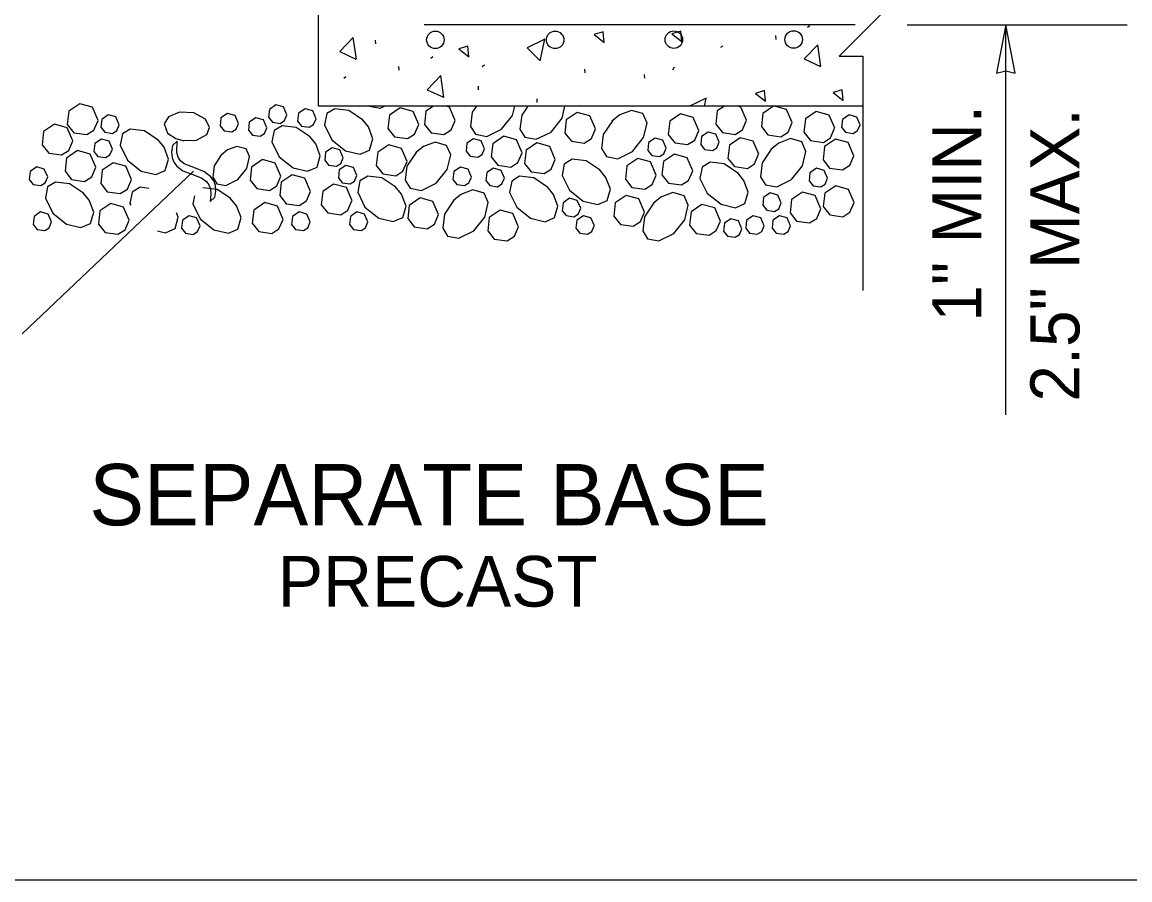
# Model space of a CAD drawing. Extents: x 99862 to 104211, y 98939 to 102076.
# Drawn here: x 100716.6 to 101077.6, y 99999.5 to 100279.2 of the extents above; entities that cross this region are included whole.
import ezdxf

# ---------------------------------------------------------------- set-up
doc = ezdxf.new("R2010")
doc.units = 0
for name, color, linetype in [('Level 1', 7, 'Continuous'), ('Level 15', 7, 'Continuous'), ('Level 17', 7, 'Continuous'), ('Level 18', 7, 'Continuous'), ('Level 19', 7, 'Continuous'), ('Level 20', 7, 'Continuous'), ('Level 23', 7, 'Continuous'), ('Level 7', 7, 'Continuous')]:
    doc.layers.add(name, color=color, linetype=linetype)

msp = doc.modelspace()

# ---------------------------------------------------------------- linework, layer by layer
at = {"layer": 'Level 1'}
msp.add_lwpolyline([(99862, 99999.5), (103151, 99999.5), (103151, 102075.5), (99862, 102075.5)], close=True, dxfattribs=at)
at = {"layer": 'Level 15'}
for p, q in [((101005.09, 100278.27), (101076.76, 100278.27)), ((101037.22, 100151.13), (101037.22, 100278.27)), ((100772.49, 100230.57), (100716.61, 100177.58))]:
    msp.add_line(p, q, dxfattribs=at)
msp.add_lwpolyline([(100990.61, 100319.79), (100990.61, 100283.53), (100998.35, 100283.53), (100982.86, 100268.05), (100990.61, 100268.05), (100990.61, 100191.69)], dxfattribs=at)
msp.add_lwpolyline([(101037.22, 100278.27), (101034.13, 100262.55), (101037.22, 100263.27), (101040.3, 100262.55)], close=True, dxfattribs=at)
at = {"layer": 'Level 17'}
for p, q in [((100813.22, 100251.79), (100813.22, 101461.47)), ((100990.61, 100251.79), (100813.22, 100251.79))]:
    msp.add_line(p, q, dxfattribs=at)
at = {"layer": 'Level 18'}
msp.add_line((100988.13, 100278.27), (100847.67, 100278.27), dxfattribs=at)
at = {"layer": 'Level 19'}
for p, q in [((100973.33, 100277.94), (100972.61, 100277.41)), ((100962.32, 100273.56), (100962.24, 100274.78)), ((100831.88, 100272.09), (100831.8, 100273.31)), ((100945, 100271.4), (100944.28, 100270.87)), ((100850.49, 100267.9), (100849.77, 100267.37)), ((100839.48, 100263.51), (100839.4, 100264.74)), ((100867.31, 100265.15), (100866.59, 100264.62)), ((100900.07, 100262.61), (100899.98, 100263.84)), ((100929.11, 100264.49), (100928.61, 100263.48)), ((100822.15, 100261.35), (100821.43, 100260.82)), ((100919.57, 100260.94), (100919.48, 100262.16)), ((100865.39, 100257.13), (100865.31, 100258.35)), ((100884.51, 100252.93), (100884.42, 100254.16))]:
    msp.add_line(p, q, dxfattribs=at)
for points in [[(100825.54, 100267.08), (100824.55, 100274.18), (100820.1, 100269.59), (100825.42, 100267.12)], [(100906.31, 100272.58), (100905.97, 100276.01), (100903, 100275.11), (100906.31, 100272.58)], [(100931.62, 100272.82), (100931.29, 100276.25), (100928.31, 100275.35), (100931.62, 100272.82)], [(100862.25, 100267.91), (100861.91, 100271.34), (100858.93, 100270.44), (100862.25, 100267.91)], [(100885.42, 100266.58), (100886.92, 100273.59), (100881.16, 100270.79), (100885.32, 100266.66)], [(100976.95, 100264.67), (100975.96, 100271.77), (100971.51, 100267.17), (100976.83, 100264.71)], [(100854.1, 100254.62), (100853.12, 100261.73), (100848.67, 100257.13), (100853.99, 100254.67)], [(100958.94, 100253.43), (100958.6, 100256.86), (100955.63, 100255.95), (100958.94, 100253.43)], [(100984.25, 100253.67), (100983.91, 100257.1), (100980.94, 100256.2), (100984.25, 100253.67)], [(100938.97, 100251.79), (100939.54, 100254.44), (100934.09, 100251.79)]]:
    msp.add_lwpolyline(points, dxfattribs=at)
at = {"layer": 'Level 20'}
for p, q in [((100765.57, 100238.94), (100765.32, 100236.8)), ((100767.11, 100240.39), (100765.57, 100238.94)), ((100767.04, 100236.7), (100767.11, 100240.39)), ((100765.32, 100236.8), (100765.46, 100235.03)), ((100765.46, 100235.03), (100766.01, 100233.51)), ((100767.47, 100235.11), (100767.04, 100236.7)), ((100768.25, 100233.92), (100767.47, 100235.11)), ((100766.01, 100233.51), (100767, 100232.17)), ((100767, 100232.17), (100768.95, 100230.66)), ((100769.45, 100233.01), (100768.25, 100233.92)), ((100771.7, 100232.13), (100769.45, 100233.01)), ((100775.81, 100230.52), (100771.7, 100232.13)), ((100768.95, 100230.66), (100772.78, 100229.25)), ((100772.78, 100229.25), (100775.16, 100228.31)), ((100775.16, 100228.31), (100776.71, 100227.19)), ((100778, 100228.9), (100775.81, 100230.52)), ((100776.71, 100227.19), (100777.49, 100226.1)), ((100779.04, 100227.48), (100778, 100228.9)), ((100779.62, 100225.88), (100779.04, 100227.48)), ((100777.49, 100226.1), (100777.95, 100224.82)), ((100777.95, 100224.82), (100778.08, 100223.09)), ((100779.44, 100222.13), (100779.75, 100224.09)), ((100779.75, 100224.09), (100779.62, 100225.88)), ((100778.08, 100223.09), (100777.9, 100220.67)), ((100777.9, 100220.67), (100779.44, 100222.13))]:
    msp.add_line(p, q, dxfattribs=at)
at = {"layer": 'Level 23'}
for points in [[(100741.35, 100247.11), (100739.52, 100251.41), (100735.37, 100252.55), (100731.8, 100250.14), (100731.33, 100245.81), (100733.46, 100243.1), (100737.67, 100242.52), (100740.02, 100243.99), (100741.35, 100247.11)], [(100748.27, 100245.68), (100747.17, 100248.26), (100744.68, 100248.94), (100742.54, 100247.49), (100742.25, 100244.9), (100743.54, 100243.27), (100746.06, 100242.92), (100747.47, 100243.81), (100748.27, 100245.68)], [(100769.09, 100240.56), (100773.47, 100240.73), (100776.76, 100242.54), (100777.7, 100244.81), (100776.41, 100247.57), (100772.55, 100249.63), (100767.89, 100249.84), (100764.26, 100248.31), (100762.88, 100245.97), (100763.96, 100243.02), (100766.73, 100241.19), (100769.28, 100240.53)], [(100787.14, 100246.18), (100786.04, 100248.75), (100783.55, 100249.44), (100781.41, 100247.99), (100781.12, 100245.39), (100782.4, 100243.77), (100784.93, 100243.42), (100786.34, 100244.3), (100787.14, 100246.17)], [(100802.93, 100248.94), (100801.83, 100251.52), (100799.34, 100252.2), (100797.21, 100250.75), (100796.92, 100248.15), (100798.2, 100246.53), (100800.73, 100246.18), (100802.14, 100247.07), (100802.93, 100248.94)], [(100812.42, 100247.66), (100811.31, 100250.24), (100808.82, 100250.92), (100806.69, 100249.48), (100806.4, 100246.88), (100807.68, 100245.25), (100810.21, 100244.9), (100811.62, 100245.79), (100812.41, 100247.66)], [(100827.57, 100247.37), (100823.07, 100250.37), (100818.47, 100250.94), (100815.88, 100249.35), (100815.17, 100245.67), (100817.55, 100240.81), (100822.05, 100237.22), (100826.78, 100236.12), (100829.86, 100237.46), (100830.92, 100241.18), (100829.47, 100245.03), (100827.4, 100247.54)], [(100829.77, 100251.79), (100833.31, 100251.11), (100834.71, 100251.79)], [(100845.86, 100245.78), (100844.02, 100250.08), (100839.87, 100251.21), (100836.31, 100248.81), (100835.83, 100244.48), (100837.96, 100241.77), (100842.18, 100241.19), (100844.53, 100242.66), (100845.85, 100245.78)], [(100846.85, 100251.79), (100846.91, 100251.78), (100846.92, 100251.79)], [(100850.63, 100251.79), (100848.21, 100250.16), (100847.73, 100245.83), (100849.87, 100243.12), (100854.08, 100242.54), (100856.43, 100244.02), (100857.76, 100247.13)], [(100857.76, 100247.13), (100855.93, 100251.43), (100854.62, 100251.79)], [(100864.66, 100251.79), (100863.33, 100249.79), (100862.76, 100245.19), (100864.35, 100242.61), (100868.03, 100241.9), (100872.89, 100244.27), (100876.48, 100248.78), (100877.18, 100251.79)], [(100881.38, 100251.79), (100879.44, 100248.87), (100878.87, 100244.26), (100880.45, 100241.68), (100884.13, 100240.97), (100888.99, 100243.35), (100892.58, 100247.85), (100893.5, 100251.79)], [(100903.51, 100244.34), (100901.68, 100248.64), (100897.53, 100249.77), (100893.97, 100247.36), (100893.49, 100243.03), (100895.62, 100240.32), (100899.83, 100239.74), (100902.19, 100241.22), (100903.51, 100244.34)], [(100909.03, 100247.05), (100906.03, 100242.55), (100905.46, 100237.94), (100907.05, 100235.36), (100910.73, 100234.65), (100915.59, 100237.03), (100919.18, 100241.53), (100920.28, 100246.26), (100918.94, 100249.34), (100915.21, 100250.39), (100911.37, 100248.94), (100908.86, 100246.88)], [(100937.2, 100243.83), (100935.37, 100248.13), (100931.22, 100249.26), (100927.66, 100246.85), (100927.18, 100242.52), (100929.31, 100239.81), (100933.52, 100239.23), (100935.88, 100240.71), (100937.2, 100243.83)], [(100945.52, 100251.79), (100943.18, 100250.21), (100942.7, 100245.87), (100944.83, 100243.16), (100949.04, 100242.58), (100951.39, 100244.06), (100952.72, 100247.18)], [(100952.72, 100247.18), (100950.89, 100251.48), (100949.75, 100251.79)], [(100961.52, 100251.79), (100958.04, 100249.44), (100957.57, 100245.11), (100959.7, 100242.4), (100963.91, 100241.82), (100966.26, 100243.29), (100967.59, 100246.41)], [(100967.59, 100246.41), (100965.76, 100250.71), (100961.81, 100251.79)], [(100981.44, 100244.59), (100979.6, 100248.89), (100975.45, 100250.02), (100971.89, 100247.61), (100971.41, 100243.28), (100973.55, 100240.57), (100977.76, 100239.99), (100980.11, 100241.47), (100981.43, 100244.59)], [(100989.72, 100245.67), (100988.62, 100248.25), (100986.13, 100248.93), (100983.99, 100247.49), (100983.7, 100244.89), (100984.99, 100243.26), (100987.51, 100242.92), (100988.92, 100243.8), (100989.72, 100245.67)], [(100733.16, 100240.46), (100731.32, 100244.76), (100727.18, 100245.89), (100723.61, 100243.48), (100723.13, 100239.15), (100725.27, 100236.44), (100729.48, 100235.86), (100731.83, 100237.34), (100733.16, 100240.46)], [(100796.37, 100244.73), (100795.27, 100247.32), (100792.78, 100248), (100790.64, 100246.55), (100790.35, 100243.95), (100791.64, 100242.33), (100794.16, 100241.98), (100795.57, 100242.87), (100796.37, 100244.74)], [(100810.44, 100241.83), (100805.93, 100244.82), (100801.33, 100245.39), (100798.75, 100243.81), (100798.04, 100240.12), (100800.41, 100235.26), (100804.92, 100231.67), (100809.65, 100230.58), (100812.72, 100231.91), (100813.78, 100235.64), (100812.33, 100239.48), (100810.27, 100241.99)], [(100760.96, 100240.74), (100756.46, 100243.74), (100751.85, 100244.31), (100749.27, 100242.72), (100748.56, 100239.04), (100750.94, 100234.18), (100755.44, 100230.59), (100760.17, 100229.49), (100763.25, 100230.83), (100764.3, 100234.55), (100762.85, 100238.4), (100760.79, 100240.91)], [(100879.54, 100236.52), (100877.71, 100240.82), (100873.56, 100241.95), (100869.99, 100239.54), (100869.51, 100235.21), (100871.65, 100232.5), (100875.86, 100231.92), (100878.21, 100233.4), (100879.54, 100236.52)], [(100943.8, 100240.04), (100942.7, 100242.62), (100940.21, 100243.3), (100938.07, 100241.86), (100937.78, 100239.26), (100939.06, 100237.63), (100941.59, 100237.29), (100943, 100238.17), (100943.8, 100240.04)], [(100746.03, 100237.76), (100744.93, 100240.33), (100742.44, 100241.01), (100740.3, 100239.57), (100740.01, 100236.97), (100741.29, 100235.35), (100743.82, 100235), (100745.23, 100235.88), (100746.03, 100237.75)], [(100781.62, 100235.97), (100779.19, 100232.32), (100778.73, 100228.6), (100780.01, 100226.5), (100782.99, 100225.93), (100786.93, 100227.85), (100789.84, 100231.5), (100790.72, 100235.33), (100789.65, 100237.82), (100786.62, 100238.68), (100783.51, 100237.51), (100781.48, 100235.84)], [(100821.23, 100234.94), (100820.13, 100237.52), (100817.64, 100238.2), (100815.5, 100236.76), (100815.22, 100234.16), (100816.5, 100232.53), (100819.02, 100232.18), (100820.44, 100233.07), (100821.23, 100234.94)], [(100842.07, 100233.72), (100840.23, 100238.02), (100836.08, 100239.15), (100832.52, 100236.75), (100832.04, 100232.41), (100834.18, 100229.71), (100838.39, 100229.12), (100840.74, 100230.6), (100842.07, 100233.72)], [(100845.04, 100236.71), (100842.04, 100232.2), (100841.47, 100227.6), (100843.06, 100225.01), (100846.74, 100224.3), (100851.6, 100226.68), (100855.19, 100231.18), (100856.29, 100235.91), (100854.95, 100238.99), (100851.23, 100240.05), (100847.38, 100238.6), (100844.87, 100236.53)], [(100867.33, 100237.91), (100866.23, 100240.48), (100863.73, 100241.17), (100861.6, 100239.72), (100861.31, 100237.12), (100862.59, 100235.5), (100865.12, 100235.15), (100866.53, 100236.03), (100867.33, 100237.9)], [(100890.39, 100234.38), (100888.56, 100238.68), (100884.41, 100239.81), (100880.85, 100237.4), (100880.37, 100233.07), (100882.51, 100230.36), (100886.71, 100229.78), (100889.07, 100231.26), (100890.39, 100234.37)], [(100926.54, 100238.08), (100925.43, 100240.66), (100922.95, 100241.34), (100920.81, 100239.9), (100920.52, 100237.3), (100921.8, 100235.67), (100924.33, 100235.33), (100925.74, 100236.21), (100926.53, 100238.08)], [(100956.67, 100236.08), (100954.83, 100240.38), (100950.68, 100241.51), (100947.12, 100239.1), (100946.64, 100234.77), (100948.78, 100232.06), (100952.99, 100231.48), (100955.34, 100232.96), (100956.66, 100236.08)], [(100960.85, 100237.84), (100957.85, 100233.34), (100957.28, 100228.74), (100958.87, 100226.15), (100962.55, 100225.44), (100967.41, 100227.82), (100971, 100232.32), (100972.09, 100237.05), (100970.76, 100240.13), (100967.04, 100241.19), (100963.19, 100239.74), (100960.68, 100237.67)], [(100987.66, 100235.62), (100985.83, 100239.93), (100981.68, 100241.06), (100978.11, 100238.65), (100977.64, 100234.32), (100979.77, 100231.61), (100983.98, 100231.03), (100986.33, 100232.51), (100987.66, 100235.63)], [(100740.63, 100231.84), (100738.79, 100236.14), (100734.64, 100237.28), (100731.08, 100234.87), (100730.6, 100230.54), (100732.74, 100227.83), (100736.95, 100227.25), (100739.3, 100228.72), (100740.63, 100231.84)], [(100904.99, 100230.91), (100900.49, 100233.91), (100895.88, 100234.48), (100893.3, 100232.9), (100892.59, 100229.21), (100894.97, 100224.35), (100899.47, 100220.76), (100904.2, 100219.67), (100907.28, 100221), (100908.33, 100224.73), (100906.88, 100228.57), (100904.82, 100231.08)], [(100923.27, 100229.33), (100921.44, 100233.63), (100917.29, 100234.76), (100913.73, 100232.35), (100913.25, 100228.02), (100915.38, 100225.31), (100919.59, 100224.73), (100921.95, 100226.21), (100923.27, 100229.32)], [(100935.18, 100230.68), (100933.34, 100234.98), (100929.19, 100236.11), (100925.63, 100233.7), (100925.15, 100229.37), (100927.29, 100226.66), (100931.5, 100226.08), (100933.85, 100227.56), (100935.18, 100230.68)], [(100724.94, 100228.69), (100723.83, 100231.27), (100721.35, 100231.95), (100719.21, 100230.51), (100718.92, 100227.91), (100720.2, 100226.28), (100722.73, 100225.93), (100724.14, 100226.82), (100724.93, 100228.69)], [(100752.24, 100227.88), (100750.4, 100232.18), (100746.26, 100233.31), (100742.69, 100230.9), (100742.21, 100226.57), (100744.35, 100223.86), (100748.56, 100223.28), (100750.91, 100224.76), (100752.24, 100227.88)], [(100800.96, 100228.91), (100799.13, 100233.21), (100794.98, 100234.35), (100791.41, 100231.94), (100790.93, 100227.61), (100793.07, 100224.9), (100797.28, 100224.32), (100799.63, 100225.8), (100800.96, 100228.91)], [(100825.69, 100229.22), (100824.59, 100231.8), (100822.1, 100232.48), (100819.96, 100231.04), (100819.67, 100228.44), (100820.95, 100226.81), (100823.48, 100226.47), (100824.89, 100227.35), (100825.69, 100229.22)], [(100863.04, 100228.63), (100861.93, 100231.21), (100859.45, 100231.89), (100857.31, 100230.45), (100857.02, 100227.85), (100858.3, 100226.22), (100860.83, 100225.88), (100862.24, 100226.76), (100863.03, 100228.63)], [(100873.79, 100228.28), (100872.69, 100230.86), (100870.2, 100231.54), (100868.06, 100230.1), (100867.77, 100227.5), (100869.06, 100225.87), (100871.58, 100225.52), (100872.99, 100226.41), (100873.79, 100228.28)], [(100949.92, 100229.93), (100945.42, 100232.93), (100940.81, 100233.5), (100938.23, 100231.91), (100937.52, 100228.23), (100939.89, 100223.37), (100944.4, 100219.78), (100949.13, 100218.68), (100952.2, 100220.02), (100953.26, 100223.74), (100951.81, 100227.59), (100949.75, 100230.1)], [(100979.12, 100228.27), (100978.02, 100230.84), (100975.53, 100231.53), (100973.39, 100230.08), (100973.1, 100227.48), (100974.38, 100225.86), (100976.91, 100225.51), (100978.32, 100226.39), (100979.12, 100228.26)], [(100810.58, 100224), (100808.74, 100228.3), (100804.59, 100229.43), (100801.03, 100227.03), (100800.55, 100222.7), (100802.69, 100219.99), (100806.9, 100219.41), (100809.25, 100220.88), (100810.57, 100224)], [(100838.38, 100225.41), (100833.87, 100228.41), (100829.27, 100228.98), (100826.69, 100227.39), (100825.98, 100223.71), (100828.35, 100218.85), (100832.86, 100215.26), (100837.59, 100214.16), (100840.66, 100215.49), (100841.72, 100219.22), (100840.27, 100223.07), (100838.21, 100225.58)], [(100887.86, 100225.37), (100883.35, 100228.37), (100878.75, 100228.94), (100876.17, 100227.35), (100875.46, 100223.67), (100877.83, 100218.81), (100882.33, 100215.22), (100887.06, 100214.12), (100890.14, 100215.45), (100891.2, 100219.18), (100889.75, 100223.03), (100887.69, 100225.54)], [(100736.59, 100223.46), (100732.08, 100226.45), (100727.48, 100227.02), (100724.89, 100225.44), (100724.18, 100221.76), (100726.56, 100216.9), (100731.06, 100213.3), (100735.79, 100212.21), (100738.87, 100213.54), (100739.93, 100217.27), (100738.48, 100221.12), (100736.41, 100223.63)], [(100757.86, 100224.97), (100755.06, 100225.32), (100752.47, 100223.73), (100751.76, 100220.05), (100752.05, 100219.46)], [(100784.63, 100221.63), (100780.12, 100224.62), (100775.53, 100225.19)], [(100824.12, 100220.96), (100822.28, 100225.26), (100818.13, 100226.4), (100814.57, 100223.99), (100814.09, 100219.66), (100816.23, 100216.95), (100820.44, 100216.37), (100822.79, 100217.84), (100824.11, 100220.96)], [(100857.29, 100221.13), (100854.29, 100216.62), (100853.72, 100212.02), (100855.3, 100209.44), (100858.99, 100208.73), (100863.85, 100211.1), (100867.44, 100215.61), (100868.53, 100220.34), (100867.2, 100223.41), (100863.47, 100224.47), (100859.63, 100223.02), (100857.12, 100220.96)], [(100922.46, 100220.25), (100919.46, 100215.75), (100918.89, 100211.14), (100920.48, 100208.56), (100924.16, 100207.85), (100929.02, 100210.22), (100932.61, 100214.73), (100933.7, 100219.46), (100932.37, 100222.53), (100928.64, 100223.59), (100924.8, 100222.14), (100922.29, 100220.08)], [(100976.94, 100218.3), (100975.11, 100222.6), (100970.96, 100223.74), (100967.39, 100221.33), (100966.92, 100217), (100969.05, 100214.29), (100973.26, 100213.71), (100975.61, 100215.19), (100976.94, 100218.3)], [(100987.76, 100220.34), (100985.92, 100224.64), (100981.77, 100225.78), (100978.21, 100223.37), (100977.73, 100219.04), (100979.87, 100216.33), (100984.08, 100215.75), (100986.43, 100217.23), (100987.75, 100220.34)], [(100751.53, 100214.59), (100749.69, 100218.9), (100745.55, 100220.03), (100741.98, 100217.62), (100741.5, 100213.29), (100743.64, 100210.58), (100747.85, 100210), (100750.2, 100211.48), (100751.53, 100214.59)], [(100772.73, 100222.53), (100772.22, 100219.93), (100774.6, 100215.06), (100779.1, 100211.47), (100783.83, 100210.38), (100786.91, 100211.71), (100787.97, 100215.44), (100786.52, 100219.29), (100784.46, 100221.79)], [(100801.64, 100214.88), (100799.81, 100219.18), (100795.66, 100220.32), (100792.1, 100217.91), (100791.62, 100213.58), (100793.75, 100210.87), (100797.96, 100210.29), (100800.32, 100211.76), (100801.64, 100214.88)], [(100852.32, 100216.42), (100850.49, 100220.72), (100846.34, 100221.85), (100842.78, 100219.44), (100842.3, 100215.11), (100844.43, 100212.4), (100848.64, 100211.82), (100851, 100213.3), (100852.32, 100216.42)], [(100898.65, 100218.48), (100897.55, 100221.07), (100895.06, 100221.74), (100892.92, 100220.3), (100892.63, 100217.7), (100893.92, 100216.08), (100896.44, 100215.73), (100897.85, 100216.61), (100898.65, 100218.48)], [(100919.49, 100217.26), (100917.65, 100221.56), (100913.5, 100222.7), (100909.94, 100220.29), (100909.46, 100215.96), (100911.6, 100213.25), (100915.81, 100212.67), (100918.16, 100214.14), (100919.49, 100217.26)], [(100964.02, 100220.23), (100962.91, 100222.81), (100960.43, 100223.49), (100958.29, 100222.05), (100958, 100219.45), (100959.28, 100217.82), (100961.81, 100217.48), (100963.22, 100218.36), (100964.01, 100220.23)], [(100726.22, 100214.02), (100725.12, 100216.6), (100722.63, 100217.28), (100720.49, 100215.84), (100720.2, 100213.24), (100721.48, 100211.61), (100724.01, 100211.26), (100725.42, 100212.15), (100726.22, 100214.02)], [(100760.7, 100211.12), (100763.37, 100210.51), (100766.45, 100211.84), (100767.51, 100215.57), (100766.95, 100217.05)], [(100810.47, 100214.02), (100809.37, 100216.6), (100806.88, 100217.28), (100804.74, 100215.84), (100804.45, 100213.24), (100805.73, 100211.61), (100808.26, 100211.26), (100809.67, 100212.15), (100810.47, 100214.02)], [(100829.32, 100214.02), (100828.21, 100216.6), (100825.73, 100217.28), (100823.59, 100215.84), (100823.3, 100213.24), (100824.58, 100211.61), (100827.11, 100211.26), (100828.52, 100212.15), (100829.31, 100214.02)], [(100878.38, 100212.46), (100876.54, 100216.76), (100872.4, 100217.89), (100868.83, 100215.48), (100868.35, 100211.15), (100870.49, 100208.44), (100874.7, 100207.86), (100877.05, 100209.34), (100878.38, 100212.46)], [(100944.18, 100214.32), (100942.34, 100218.63), (100938.19, 100219.76), (100934.63, 100217.35), (100934.15, 100213.02), (100936.29, 100210.31), (100940.5, 100209.73), (100942.85, 100211.21), (100944.18, 100214.32)], [(100774.59, 100212.75), (100773.49, 100215.33), (100771, 100216.01), (100768.86, 100214.56), (100768.58, 100211.97), (100769.86, 100210.34), (100772.38, 100209.99), (100773.8, 100210.88), (100774.59, 100212.75)], [(100903.11, 100212.77), (100902.01, 100215.35), (100899.52, 100216.03), (100897.38, 100214.58), (100897.09, 100211.98), (100898.37, 100210.36), (100900.9, 100210.01), (100902.31, 100210.9), (100903.1, 100212.77)], [(100951.21, 100211.82), (100950.11, 100214.4), (100947.62, 100215.08), (100945.48, 100213.64), (100945.19, 100211.04), (100946.47, 100209.41), (100949, 100209.07), (100950.41, 100209.95), (100951.21, 100211.82)], [(100958.44, 100212.77), (100957.34, 100215.35), (100954.85, 100216.03), (100952.71, 100214.58), (100952.43, 100211.98), (100953.71, 100210.36), (100956.23, 100210.01), (100957.65, 100210.9), (100958.44, 100212.77)], [(100967.06, 100212.77), (100965.96, 100215.35), (100963.47, 100216.03), (100961.33, 100214.58), (100961.04, 100211.98), (100962.33, 100210.36), (100964.85, 100210.01), (100966.26, 100210.9), (100967.06, 100212.77)]]:
    msp.add_lwpolyline(points, dxfattribs=at)
at = {"layer": 'Level 7'}
for centre in [(100851.3, 100273.4), (100890.33, 100273.4), (100929.03, 100273.46), (100968.08, 100273.52)]:
    msp.add_circle(centre, 2.85, dxfattribs=at)

# ---------------------------------------------------------------- texts
at = {"layer": 'Level 20'}
for s, height, rotation, p in [('1" MIN.', 16, 90, (101029.22, 100181.55)), ('2.5" MAX.', 16, 90, (101061.22, 100155.44)), ('SEPARATE BASE', 20, 360, (100738.5, 100115.11)), ('PRECAST', 16.5, 360, (100799.98, 100088.61))]:
    msp.add_text(s, height=height, rotation=rotation, dxfattribs=at).set_placement(p)

doc.saveas('drawing.dxf')
